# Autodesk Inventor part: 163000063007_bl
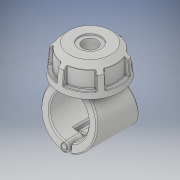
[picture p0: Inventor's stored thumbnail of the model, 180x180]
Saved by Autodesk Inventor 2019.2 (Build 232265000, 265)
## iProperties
Created: 2022-02
Part Number: 163000063007_bl
Material: Generic
Description: Plassadle Threaded 63x3/4''
Document SubType Name: Modeling
Designer: comp2
Density: 1 g/cm^3
Appearance: Default
Author: comp2
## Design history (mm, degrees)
derived "16300.ipt"
feature "Solid1::16300.ipt" dims "ScaleForDerivedMember" = 10
feature "Solid2::16300.ipt" dims "ScaleForDerivedMember" = 10
feature "Solid3::16300.ipt" dims "ScaleForDerivedMember" = 10
feature "Solid4::16300.ipt" dims "ScaleForDerivedMember" = 10
tag "TaggingFeature1"
body "Solid1"
body "Solid2"
body "Solid3"
body "Solid4"
other parameters: "d0" = 63 [user parameter], "d2" = 91 [user parameter], "d3" = 31.5 [user parameter], "d7" = 86.45 [user parameter], "d8" = 85 deg [user parameter], "d9" = 45 deg [user parameter], "d10" = 102 [user parameter], "d11" = 49 [user parameter], "d12" = 31.8185 [user parameter], "d13" = 42.84 [user parameter], "d14" = 36.1755 [user parameter], "d42" = 2.8 [user parameter], "d49" = 1.82 [user parameter], "d50" = 89 [user parameter], "d51" = 0 [user parameter], "d52" = 19.6 [user parameter], "d53" = 50.05 [user parameter], "d54" = 31.15 [user parameter], "d55" = 0 [user parameter], "d56" = 17.8 [user parameter], "d57" = 17.8 [user parameter], "d59" = 0 [user parameter], "d60" = 89 [user parameter], "d61" = 0 [user parameter], "d62" = 31.15 [user parameter], "d63" = 0 [user parameter], "d65" = 0 [user parameter], "d67" = 0 [user parameter], "d69" = 0 [user parameter], "d70" = 1 [user parameter], "d71" = 85.44 [user parameter], "d72" = 0 [user parameter], "d73" = 2 [user parameter], "d78" = 86.7 [user parameter], "d79" = 5.1 [user parameter], "d80" = 60 deg [user parameter], "d81" = 5.1 [user parameter], "d84" = 0 [user parameter], "d85" = 1 [user parameter], "d87" = 360 deg [user parameter], "d122" = 49 [user parameter], "d124" = 42.80128 [user parameter], "d125" = 2.27275 [user parameter], "d127" = 136 [user parameter], "d129" = 24.117 [user parameter], "d130" = 20.49945 [user parameter], "d131" = 31.85 [user parameter], "d132" = 45 deg [user parameter], "d133" = 22.295 [user parameter], "d134" = 12.0585 [user parameter], "d136" = 0 [user parameter], "d138" = 0 [user parameter], "d" = 63 [user parameter], "d1" = 25 [user parameter], "B" = 91 [user parameter], "L" = 89 [user parameter], "E_" = 54 [user parameter], "E1" = 102 [user parameter], "H1" = 136 [user parameter], "H2" = 49 [user parameter], "H3" = 78 [user parameter], "H_costum" = 49 [user parameter], "Rp" = 24.117 [user parameter], "d128" = 45.455 [user parameter]
